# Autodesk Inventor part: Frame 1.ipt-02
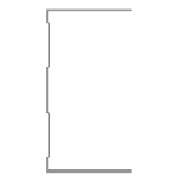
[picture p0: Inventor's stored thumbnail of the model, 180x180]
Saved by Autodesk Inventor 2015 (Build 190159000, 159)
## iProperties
IsCustomPart: 1
Created: 2015-04
Part Number: Frame 1.ipt-02
Material: Aluminum 6061
Description: Kévin Novo
Document SubType Name: Modeling
Standard: Kevin
Designer: suporte
Standards Organization: Kevin
Language: en-US
Size Designation: (Unnamed 2)
Categories: <MemberInstance><Categories><Category DisplayName="Structural Shapes" InternalName="089c4875-fa83-4c05-b084-43b9cc11f5ed" Mnemonic="GRDR"><CategoryParameter Dis
Density: 2.7 g/cm^3
Appearance: Aluminum - Flat
_CCFamilyMember: 2
_CCFamilyDisplayName: Kévin - Kévin Novo
_FrameMemberDoc: Frame Member File
_Version: 15.0.0
_GetPNFromCC: 1
G_W: 50,000 mm
G_H: 75,000 mm
G_L: 518,599 mm
Author: suporte
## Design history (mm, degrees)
node "Start Plane"
node "End Plane"
sketch "Sketch"
  geometry: L1 (24.7, 37.5)-(24.7, 36.9); L2 (24.7, 36.9)-(-24.7, 36.9); L3 (-24.7, -36.9)-(24.7, -36.9); L4 (24.7, -36.9)-(24.7, -37.5); L5 (24.7, -37.5)-(-25.3, -37.5); L6 (-25.3, 37.5)-(24.7, 37.5); L7 (-24.7, 36.9)-(-24.7, 31.9); L8 (-24.7, 31.9)-(-23.3, 30.5); L9 (-23.3, 30.5)-(-23.3, 10.934); L10 (-23.3, 10.934)-(-24.7, 9.534); L11 (-24.7, 9.534)-(-24.7, -9.534); L12 (-24.7, -9.534)-(-23.3, -10.934); L13 (-23.3, -10.934)-(-23.3, -30.5); L14 (-23.3, -30.5)-(-24.7, -31.9); L15 (-24.7, -31.9)-(-24.7, -36.9); L16 (-25.3, -37.5)-(-25.3, -31.651); L17 (-25.3, -31.651)-(-23.9, -30.251); L18 (-23.9, -30.251)-(-23.9, -11.183); L19 (-23.9, -11.183)-(-25.3, -9.783); L20 (-25.3, -9.783)-(-25.3, 9.783); L21 (-25.3, 9.783)-(-23.9, 11.183); L22 (-23.9, 11.183)-(-23.9, 30.251); L23 (-23.9, 30.251)-(-25.3, 31.651); L24 (-25.3, 31.651)-(-25.3, 37.5); L25 (-25.3, 0)-(30.37, 0); 3 further points
  constraints: 50 end point, 10 point on line, 9 parallel, 5 perpendicular, 4 equal length, 3 midpoint, 3 vertical, 2 vertical alignment, 1 collinear, 1 horizontal, 1 horizontal alignment
  dimensions: "d3" = 0.6 distance of L1.start L1.end (= d6); "d5" = 75 distance between parallel lines of L5 L6; "d6" = 0.6 distance between parallel lines of L24 L7 (= d8); "d7" = 0.6 distance between parallel lines of L8 L23 (= d8); "d8" = 0.6 distance between parallel lines of L22 L9 (= d12); "Espessura" = 0.6 distance between parallel lines of L17 L14; "d10" = 0.6 distance between parallel lines of L13 L18 (= Espessura); "d11" = 0.6 distance between parallel lines of L12 L19 (= Espessura); "d12" = 0.6 distance between parallel lines of L21 L10 (= d11); "d13" = 5 distance of L2.end L7.end; "d15" = 135 deg angle of L9 L8; "d16" = 2 distance between parallel lines of L24 L9; "d17" = 50 distance of L6.start L1.start
extrude "Body" join sketch "Sketch" stored distance "d24" = 0.13; taper "d25" = 0 deg
node "Driven Length"
  sketch "Sketch10"
    geometry: L1 (0, 0)-(10, 0) reference
    constraints: 2 end point, 1 horizontal
  workplane "Work Plane7"
  sketch "Sketch11"
    geometry: L1 (-2, 0)-(12, 0) reference; L2 (-2, 518.599)-(12, 518.599) reference
    dimensions: "d27" = 518.59902 distance between parallel lines of L1 L2 (derived)
body "Solid1"
other parameters: "tamanho" = 518.59902, "G_OFFSET_START" = 0 [user parameter; used in 1 equation term], "G_OFFSET_END" = 0 [user parameter; used in 1 equation term], "d22" = 0 (computed from G_OFFSET_START), "d23" = 518.59902 (= tamanho + G_OFFSET_END), "G_L" = 518.59902 (= d27) [user parameter], "d34" = 90 deg
